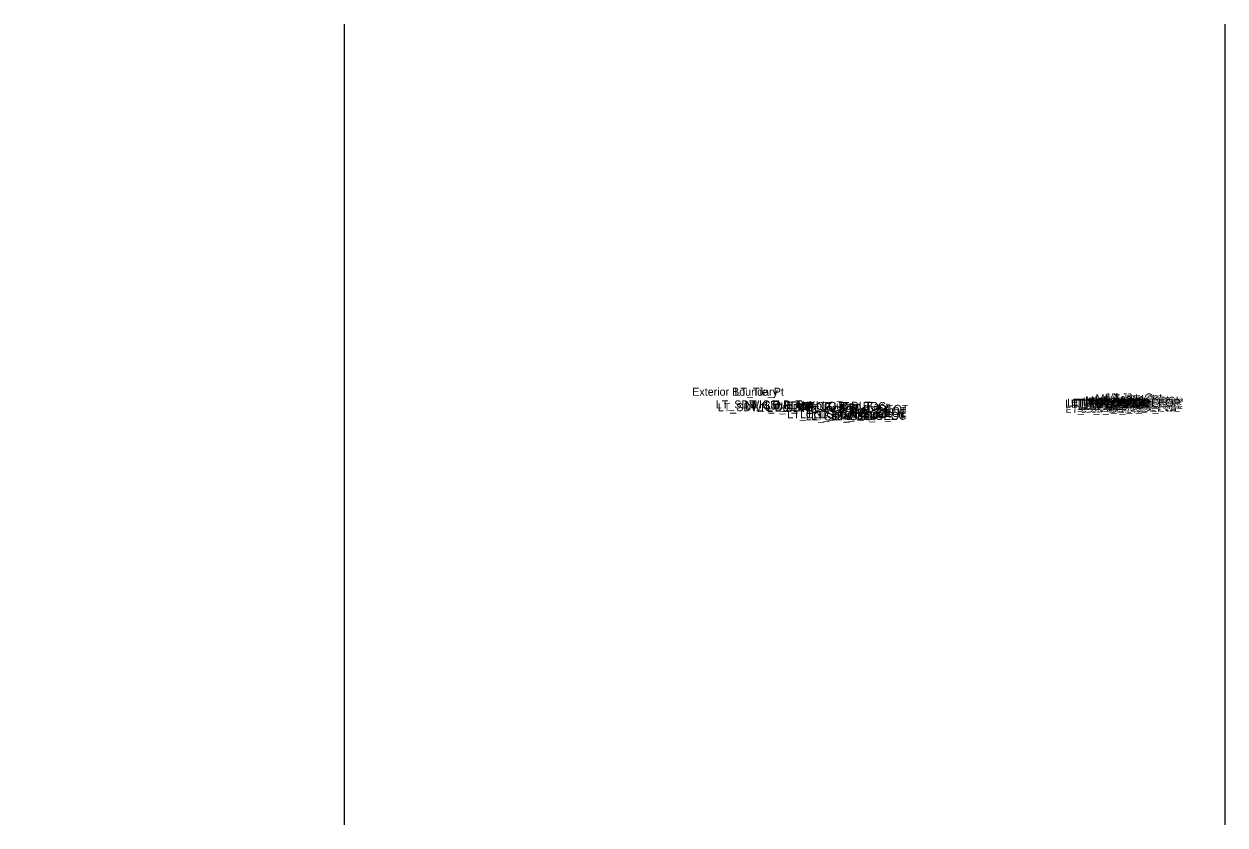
# Model space of a CAD drawing. Extents: x 0 to 6300, y -50 to 9550.
# Drawn here: x 3000 to 3150, y 2950 to 3050 of the extents above; entities that cross this region are included whole.
import ezdxf

# ---------------------------------------------------------------- set-up
doc = ezdxf.new("R2010")
doc.units = 0
for name, color, linetype in [('Default', 7, 'Continuous'), ('Prop XS Exc Vertical Line 1', 7, 'Continuous'), ('Prop XS Exc Vertical Line 2', 7, 'Continuous')]:
    doc.layers.add(name, color=color, linetype=linetype)

msp = doc.modelspace()

# ---------------------------------------------------------------- linework, layer by layer
at = {"layer": 'Prop XS Exc Vertical Line 1'}
msp.add_line((3040, 3050), (3040, 2950), dxfattribs=at)
at = {"layer": 'Prop XS Exc Vertical Line 2'}
msp.add_line((3150, 3050), (3150, 2950), dxfattribs=at)

# ---------------------------------------------------------------- texts
at = {"layer": 'Default'}
for s, height, p in [('Exterior Boundary', 1, (3083.46, 3003.59)), ('LT_Tie_Pt', 1, (3088.74, 3003.59)), ('LT_SDWK_Out_Top', 1, (3086.41, 3002)), ('LT_CSLP_Pnt', 1, (3089.92, 3002)), ('LT_PV2_OEEOP', 1, (3130.04, 3002.09)), ('LT_PV1_OEEOP', 1, (3130.27, 3002.22)), ('LT_PV2_IEEOP', 1, (3130.8, 3002.09)), ('LT_PV1_IEEOP', 1, (3131.04, 3002.22)), ('LT_PV2_PGL1', 1, (3131.63, 3002.09)), ('LT_PV2_PGL', 1, (3132.01, 3002.09)), ('LT_PV1_PGL', 1, (3132.25, 3002.34)), ('MI_Face In', 1, (3132.55, 3002.51)), ('MI_Bot In', 1, (3133.72, 3002.34)), ('MI_Top In', 1, (3133.84, 3002.76)), ('RT_PV2_OEEOP', 1, (3133.92, 3002.21)), ('RT_PV1_OEEOP', 1, (3134.16, 3002.34)), ('RT_PV2_IEEOP', 1, (3134.68, 3002.21)), ('RT_PV1_IEEOP', 1, (3134.92, 3002.34)), ('MI_Top Out', 1, (3135.1, 3002.88)), ('MI_Crown', 1, (3135.24, 3002.91)), ('MI_Face Out', 1, (3135.31, 3002.63)), ('RT_PV2_PGL1', 1, (3135.52, 3002.21)), ('RT_PV2_PGL', 1, (3135.9, 3002.21)), ('RT_PV1_PGL', 1, (3136.13, 3002.46)), ('MI_Bot Out', 1, (3136.5, 3002.46)), ('LT_SDWK_Out_Bot', 1, (3086.65, 3001.66)), ('LT_Sub_Trench_Out_DLT', 1, (3090.06, 3001.85)), ('LT_SDWK_In_Top', 1, (3092.56, 3001.9)), ('LT_SDWK_In_Bot', 1, (3092.81, 3001.56)), ('LT_CG1_Shelf_Out', 1, (3095.33, 3000.77)), ('LT_CG_Top_BOC', 1, (3096.66, 3001.81)), ('LT_CG_Bot_BOC', 1, (3096.94, 3000.79)), ('LT_CG_Top_Face', 1, (3097.2, 3001.81)), ('LT_Sub_OEOP', 1, (3097.63, 3000.52)), ('LT_CG_Top_Gut', 1, (3097.72, 3001.31)), ('LT_Sub_OEOT_CG', 1, (3098.29, 3000.61)), ('LT_PV2_OEOT', 1, (3100.84, 3001.2)), ('LT_PV3_OEOT', 1, (3100.84, 3000.95)), ('LT_Sub_OEOT', 1, (3100.89, 3000.57)), ('LT_PV1_OEOT', 1, (3101.08, 3001.45)), ('LT_CG_Bot_IE', 1, (3101.19, 3000.86)), ('LT_PV3_OEEOP', 1, (3130.04, 3001.84)), ('LT_Sub_OEEOP', 1, (3130.08, 3001.47)), ('LT_PV3_PGL1', 1, (3131.63, 3001.84)), ('LT_PV4_PGL', 1, (3132.01, 3001.47)), ('RT_PV3_OEEOP', 1, (3133.92, 3001.96)), ('RT_Sub_OEEOP', 1, (3133.96, 3001.59)), ('RT_PV3_PGL1', 1, (3135.52, 3001.96)), ('RT_PV4_PGL', 1, (3135.9, 3001.59)), ('-', 0.0001, (3000, 3000))]:
    msp.add_text(s, height=height, dxfattribs=at).set_placement(p)

doc.saveas('drawing.dxf')
